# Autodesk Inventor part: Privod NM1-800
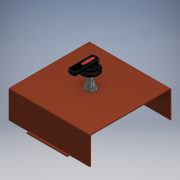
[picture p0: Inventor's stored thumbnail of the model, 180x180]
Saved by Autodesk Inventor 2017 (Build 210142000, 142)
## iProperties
Part Number: Privod NM1-800
Material: Типовые
Document SubType Name: Modeling
Designer: RSagdiev
Density: 1 g/cm^3
Appearance: По умолчанию
Author: RSagdiev
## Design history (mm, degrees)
sketch "Эскиз1"
  geometry: L1 (-52.5, 111.5)-(52.5, 111.5); L2 (52.5, 111.5)-(52.5, 103); L3 (52.5, 103)-(28.25, 103); L4 (-52.5, 103)-(-52.5, 111.5); L5 (0, 0)-(119.698, 0); L6 (0, 0)-(-104.809, 0); L7 (0, 94.88)-(0, -60.954); L8 (-28.25, 103)-(-24.25, 103); L9 (-24.25, 103)-(-24.25, 108); L10 (-26.25, 110)-(-26.25, 110); L11 (-28.25, 108)-(-28.25, 103); L12 (24.25, 103)-(24.25, 108); L13 (26.25, 110)-(26.25, 110); L14 (28.25, 103)-(24.25, 103); L15 (28.25, 108)-(28.25, 103); L16 (-28.25, 103)-(-52.5, 103); L17 (-24.25, 103)-(-28.25, 103); L18 (24.25, 103)-(-24.25, 103); L19 (28.25, 103)-(24.25, 103); A1 r 2 centre (-26.25, 108) between (-26.25, 110) and (-28.25, 108); A2 r 2 centre (-26.25, 108) between (-24.25, 108) and (-26.25, 110); A3 r 2 centre (26.25, 108) between (26.25, 110) and (24.25, 108); A4 r 2 centre (26.25, 108) between (28.25, 108) and (26.25, 110); 5 further points
  constraints: 38 end point, 10 point on line, 10 symmetric about line, 8 parallel, 8 point on circle, 4 centre point, 4 horizontal, 4 tangent, 2 perpendicular, 1 concentric, 1 midpoint, 1 vertical, 2 other
  dimensions: "d0" = 103 distance between parallel lines of L3 L6 (= 0.5 x Высота); "d1" = 8.5 distance of L1.end L2.end; "d2" = 105 distance between parallel lines of L2 L4 (= 0.5 x Ширина); "d3" = 4 distance of point (-28.25, 110) point (-24.25, 110); "d4" = 7 distance of point (-24.25, 110) L8.end; "d5" = 2 radius of A1 (derived); "d6" = 26.25 distance from line of L4 A1.centre (= 0.25 x d2)
extrude "Выдавливание1" new body sketch "Эскиз1" distance "d7" = 2; taper "d8" = 0 deg
mirror "Зеркальное отражение1"
sketch "Эскиз2"
  geometry: L1 (-52.5, 111.5)-(-52.5, 103) reference; L2 (52.5, 103)-(52.5, 111.5) reference; L3 (-52.5, -111.5)-(-52.5, -103) reference; L4 (52.5, -103)-(52.5, -111.5) reference; L5 (-105, 105)-(105, 105); L6 (105, 105)-(105, 103); L7 (105, 103)-(-105, 103); L8 (-105, 103)-(-105, 105); L9 (-52.5, 103)-(-28.25, 103) reference
  constraints: 8 end point, 2 parallel, 1 collinear, 1 horizontal, 1 perpendicular
  dimensions: "d13" = 210 distance of L5.start L5.end (= Ширина); "d14" = 2 distance of L5.end L6.end; "d15" = 52.5 distance between parallel lines of L1 L8 (= 0.25 x d13)
extrude "Выдавливание2" join sketch "Эскиз2" distance "d11" = 72 (computed from H1); taper "d12" = 0 deg
mirror "Зеркальное отражение2"
sketch "Эскиз3"
  geometry: L1 (-105, 105)-(-52.5, 105) reference; L2 (105, -105)-(-105, -105) reference; L3 (-105, 105)-(105, 105); L4 (105, 105)-(105, -105); L5 (105, -105)-(-105, -105); L6 (-105, -105)-(-105, 105); 1 further point
  constraints: 8 end point, 2 parallel, 1 horizontal, 1 perpendicular
extrude "Выдавливание3" join sketch "Эскиз3" distance "d16" = 2; taper "d17" = 0 deg
fillet "Сопряжение1" dims "d18" = 2
sketch "Эскиз4"
  geometry: L1 (105, -101)-(-105, -101) reference; L2 (105, -101)-(105, 101) reference; L3 (-105, 101)-(105, 101) reference; L4 (-105, 101)-(-105, -101) reference; L5 (-105, 101)-(-105, -101) reference; L6 (-105, -101)-(105, 101); L7 (105, -101)-(105, 101) reference; L8 (-105, 101)-(105, -101); C1 r 5 at (0, 0); 1 further point
  constraints: 4 end point, 1 centre point, 1 coincident
  dimensions: "d19" = 10 diameter of C1
extrude "Выдавливание4" cut sketch "Эскиз4" distance "d20" = 10; taper "d21" = 0 deg
sketch "Эскиз5"
  geometry: C1 r 5 at (0, 0) reference; C2 r 5 at (0, 0); C3 r 8 at (0, 0); 1 further point
  constraints: 2 centre point, 2 coincident
  dimensions: "d22" = 16 diameter of C3
extrude "Выдавливание5" new body sketch "Эскиз5" distance "d23" = 25.33333 (= 0.333333 x H1); taper "d24" = 0 deg
sketch "Эскиз6"
  geometry: C1 r 5 at (0, 0) reference; C2 r 5 at (0, 0); 1 further point
  constraints: 1 centre point, 1 coincident
extrude "Выдавливание6" new body sketch "Эскиз6" distance "d25" = 75.33333 (computed from H1); taper "d26" = 0 deg
sketch "Эскиз7"
  geometry: C1 r 5 at (0, 0) reference; C2 r 13 at (0, 0); C3 r 8 at (0, 0); C4 r 5 at (0, 0); 1 further point
  constraints: 3 centre point, 3 coincident
  dimensions: "d27" = 26 diameter of C2; "d28" = 16 diameter of C3; "d29" = 10 diameter of C4
extrude "Выдавливание7" new body sketch "Эскиз7" distance "d30" = 5; taper "d31" = 0 deg
extrude "Выдавливание8" join sketch "Эскиз7" distance "d32" = 20; taper "d33" = 0 deg
sketch "Эскиз8"
  geometry: C1 r 7 at (0, 0); 1 further point
  constraints: 1 centre point, 1 coincident
  dimensions: "d34" = 14 diameter of C1
extrude "Выдавливание9" new body sketch "Эскиз8" distance "d35" = 3; taper "d36" = 0 deg
fillet "Сопряжение2" dims "d37" = 3
sketch "Эскиз9"
  geometry: L1 (1, 13.17)-(-1, 13.17); L2 (-1, 13.17)-(-1, -13.17); L3 (-1, -13.17)-(1, -13.17); L4 (1, -13.17)-(1, 13.17); L5 (1, 13.17)-(-1, -13.17); L6 (-1, 13.17)-(1, -13.17); L7 (17.109, -1)-(-17.109, -1); L8 (-17.109, -1)-(-17.109, 1); L9 (-17.109, 1)-(17.109, 1); L10 (17.109, 1)-(17.109, -1); L11 (17.109, -1)-(-17.109, 1); L12 (-17.109, -1)-(17.109, 1); C1 r 4 at (0, 0) reference; C2 r 5 at (0, 0) reference; 1 further point
  constraints: 24 end point, 4 midpoint, 4 parallel, 2 horizontal, 2 perpendicular
  dimensions: "d38" = 2 distance of L3.end L2.end; "d39" = 2 distance of L7.end L8.end
extrude "Выдавливание10" cut sketch "Эскиз9" distance "d40" = 1; taper "d41" = 0 deg
sketch "Эскиз10"
  geometry: C1 r 17.5 at (0, 0); A1 r 4 centre (0, 0) between (1, -3.873) and (3.873, -1) reference; 1 further point
  constraints: 1 centre point, 1 coincident
  dimensions: "d42" = 35 diameter of C1
extrude "Выдавливание11" new body sketch "Эскиз10" distance "d43" = 6; taper "d44" = 0 deg; dims "d48" = 3, "d49" = 0
sketch "Эскиз11"
  geometry: C1 r 7 at (0, 0); C2 r 22.5 at (0, 0); 1 further point
  constraints: 2 centre point, 1 coincident
  dimensions: "d45" = 45 diameter of C2
extrude "Выдавливание12" join sketch "Эскиз11" distance "d46" = 6; taper "d47" = 0 deg
sketch "Эскиз12"
  geometry: L1 (-4, -49.361)-(4, -49.361); L2 (10, -43.361)-(10, 10.738); L3 (-10, 10.738)-(-10, -43.361); L4 (-10, -49.361)-(10, 14.361); L5 (10, -49.361)-(-10, 14.361); L6 (-12, 12.738)-(12, 12.738); A1 r 17.5 centre (0, 0) between (10, 14.361) and (0, -17.5) reference; A2 r 17.5 centre (0, 0) between (10, 14.361) and (0, -17.5) reference; A3 r 6 centre (-4, -43.361) between (-10, -43.361) and (-4, -49.361); A4 r 6 centre (4, -43.361) between (4, -49.361) and (10, -43.361); A5 r 2 centre (-12, 10.738) between (-10, 10.738) and (-12, 12.738); A6 r 2 centre (12, 10.738) between (12, 12.738) and (10, 10.738); A7 r 17.5 centre (0, 0) between (12, 12.738) and (-12, 12.738)
  constraints: 16 point on circle, 12 end point, 8 tangent, 6 point on line, 5 centre point, 2 equal radius, 2 horizontal, 2 midpoint, 1 coincident, 1 parallel, 1 perpendicular
  dimensions: "d63" = 20 distance of L4.end L5.end; "d64" = 6 radius of A3; "d66" = 10 distance from line of A1.centre L3; "d67" = 2 radius of A5; "d68" = 2 radius of A6 (derived)
extrude "Выдавливание13" join sketch "Эскиз12" distance "d55" = 10; taper "d56" = 0 deg
fillet "Сопряжение9" dims "d69" = 1
fillet "Сопряжение10" dims "d70" = 1
sketch "Эскиз13"
  geometry: L1 (0, 7.748)-(0, -17.5); L2 (-4, 7.748)-(-4, -17.5); L3 (4, -17.5)-(4, 7.748); A1 r 17.5 centre (0, 0) between (17.5, 0) and (0, -17.5) reference; A2 r 4 centre (0, 7.748) between (4, 7.748) and (-4, 7.748); A3 r 4 centre (0, -17.5) between (-4, -17.5) and (4, -17.5); 2 further points
  constraints: 8 end point, 5 point on circle, 4 tangent, 2 centre point, 1 midpoint, 1 parallel, 1 vertical
  dimensions: "d71" = 8 diameter of A3
extrude "Выдавливание14" cut sketch "Эскиз13" distance "d72" = 0.1; taper "d73" = 0 deg
sketch "Эскиз14"
  geometry: L1 (0, 9.652)-(1.649, 6.796); L2 (1.649, 6.796)-(-1.649, 6.796); L3 (-1.649, 6.796)-(0, 9.652); A1 r 4 centre (0, 7.748) between (4, 7.748) and (-4, 7.748) reference; 2 further points
  constraints: 6 end point, 1 coincident, 7 other
extrude "Выдавливание15" join sketch "Эскиз14" distance "d74" = 0.1; taper "d75" = 0 deg
node "Твердое тело1"
node "Спроецированная петля1"
node "Твердое тело2"
node "Твердое тело3"
node "Твердое тело4"
node "Твердое тело5"
node "Спроецированная петля2"
node "Твердое тело6"
node "Спроецированная петля3"
other parameters: "H1" = 76 [user parameter; used in 3 equation terms], "Высота" = 206 [user parameter; used in 1 equation term], "Ширина" = 210 [user parameter; used in 2 equation terms]
